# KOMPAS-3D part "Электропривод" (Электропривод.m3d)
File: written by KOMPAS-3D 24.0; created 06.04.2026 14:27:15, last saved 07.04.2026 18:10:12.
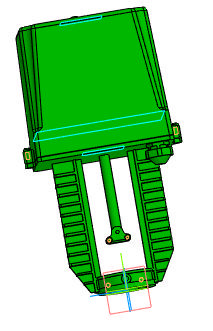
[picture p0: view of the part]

Document properties: Автор: R2D2; Полное имя файла: E:\Работа\Зайцев\Солянка\VSR1-13V-PED-F Клапан запорно-регулирующий DN.ru\DN80\исходные материалы\Электропривод.m3d

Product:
- Body: Тело 1  | qty 1
    Масса: 33.559685
- Body: Тело 2  | qty 1
    Масса: 33.559685
- Body: Тело 3  | qty 1
    Масса: 33.559685
- Component [standard]: Hexagon socket head cap screw ISO 4762 - М4 x 10  | qty 1  | Материал: Не определено (density 0 kg/m3); Масса: 0.0018; Рассекать на разрезах: no; source file: C:\Program Files\ASCON\KOMPAS-3D v24\Libs\PolynomLib\DATA\vault\Methods\Kompas\3D\PLib_Screw_DIN_7984_1500.m3d
- Component [standard]: Hexagon socket head cap screw ISO 4762 - М4 x 10  | qty 1  | Материал: Не определено (density 0 kg/m3); Масса: 0.0018; Рассекать на разрезах: no
- Component [standard]: Cheese head screw ISO 7048 - М5 x 10 - H  | qty 1  | Материал: Не определено (density 0 kg/m3); Масса: 0.00255; Рассекать на разрезах: no; source file: C:\Program Files\ASCON\KOMPAS-3D v24\Libs\PolynomLib\DATA\vault\Methods\Kompas\3D\PLib_Screw_ISO_7048_1500.m3d
- Component [standard]: Cheese head screw ISO 7048 - М5 x 10 - H  | qty 1  | Материал: Не определено (density 0 kg/m3); Масса: 0.00255; Рассекать на разрезах: no
- Component [standard]: (unnamed)  | qty 1  | Материал: Не определено (density 0 kg/m3); Масса: 0.00146; Рассекать на разрезах: no; additional columns: М6 x 10; Hexagon socket set screw; ISO 4026; source file: C:\Program Files\ASCON\KOMPAS-3D v24\Libs\PolynomLib\DATA\vault\Methods\Kompas\3D\PLib_Set_Screws_ISO_1100.m3d
- Component [standard]: (unnamed)  | qty 1  | Материал: Не определено (density 0 kg/m3); Масса: 0.00146; Рассекать на разрезах: no; additional columns: М6 x 10; Hexagon socket set screw; ISO 4026
- Component [detail]: Деталь  | qty 1  | Масса: 0.134709; Автор: R2D2; source file: ручка.m3d
- Component [detail]: Деталь  | qty 1  | Масса: 0.106559; Автор: R2D2; source file: кабельный зажим.m3d
- Part/product: Электропривод
    Масса: 0.101125

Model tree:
1. Низ
2. Элемент вращения:1
     Угол 1 = 360
3. Эскиз:4  (with: Ребро.Элемент вращения:1, Грань.Элемент вращения:1)
4. Элемент выдавливания:3
     Расстояние 1 = 35
5. Эскиз:9
6. Элемент выдавливания:6
     Расстояние 2 = 35
7. Эскиз:3  (with: Грань.Элемент вращения:1)
8. Элемент выдавливания:2
9. Эскиз:2  (with: Грань.Элемент вращения:1, Ребро.Элемент выдавливания:2)
10. Элемент выдавливания:1
11. Массив по концентрической сетке:1  (with: Элемент выдавливания:1, Эскиз:2, Грань.Элемент выдавливания:2)  (5 pattern instances)
     Шаг 2 = 360
12. Смещенная плоскость:1
     Расстояние = 327
13. Смещенная плоскость:2
     Расстояние = 169
14. крышка
15. Элемент выдавливания:4
     Расстояние 2 = 158
16. Уклон:1  (with: Грань.Элемент выдавливания:4)
     Угол уклона = 2
17. Эскиз:6  (with: Грань.Элемент выдавливания:4, Вершина.Элемент выдавливания:4)
18. Смещенная плоскость:3  (with: Грань.Элемент выдавливания:4)
     Расстояние = 128
19. Эскиз:7  (with: Ребро.Элемент выдавливания:4)
20. Элемент по сечениям:1
21. Скругление:26  (with: Ребро.Элемент выдавливания:4, Ребро.Элемент по сечениям:1, Грань.Элемент по сечениям:1)
     Радиус = 5
22. Массив по концентрической сетке:3  (with: Элемент по сечениям:1, Эскиз:6, Смещенная плоскость:3, Эскиз:7, Скругление:26)  (4 pattern instances)
     Шаг 2 = 360
23. Скругление:27  (with: Грань.Элемент выдавливания:4)
     Радиус = 5
24. уши  (with: Грань.Элемент выдавливания:4)
25. Элемент выдавливания:5
     Расстояние 2 = 15
26. Скругление:29  (with: Ребро.Элемент выдавливания:5)
     Радиус = 5
27. Эскиз:10  (with: Грань.Элемент выдавливания:4)
28. Элемент выдавливания:7
     Расстояние 1 = 0.5
29. Эскиз:11  (with: Грань.Элемент выдавливания:7, Ребро.Элемент выдавливания:4, Ребро.Скругление:26, Ребро.Элемент выдавливания:5, Ребро.Скругление:29)  (labels: Ребро.Скругление:26.Экземпляр ( 1, 4 ); Ребро.Скругление:26.Экземпляр ( 1, 3 ); Ребро.Скругление:26.Экземпляр ( 1, 2 ))
30. Элемент выдавливания:8
     Расстояние 1 = 5
31. РЕБРО  (with: Ребро.Элемент вращения:1, Ребро.Элемент выдавливания:8)
32. Элемент выдавливания:9
     Расстояние 1 = 4
33. Эскиз:13  (with: Ребро.Элемент выдавливания:9, Ребро.Элемент выдавливания:8, Грань.Элемент вращения:1, Вершина.Элемент вращения:1, Вершина.Элемент выдавливания:9, Ребро.Элемент вращения:1)
34. Элемент выдавливания:10
     Толщина стенки 2 = 3; Расстояние 1 = 20
35. Фаска:6  (with: Ребро.Элемент выдавливания:9)
     Угол = 60; Длина 1 = 20; Длина 2 = 34.641
36. Эскиз:14  (with: Вершина.Фаска:6, Ребро.Элемент выдавливания:10)
37. Элемент выдавливания:11
     Толщина стенки 1 = 3; Расстояние 1 = 20
38. Скругление:30  (with: Ребро.Элемент выдавливания:11)
     Радиус = 2
39. Массив по сетке:1  (with: Элемент выдавливания:11, Скругление:30, Ребро.Элемент выдавливания:9)  (10 pattern instances)
     Шаг 1 = 12; Угол раствора = 90
40. Эскиз:15  (with: Ребро.Элемент выдавливания:10, Ребро.Фаска:6, Ребро.Элемент выдавливания:11)
41. Элемент выдавливания:12
     Толщина стенки 2 = 2; Расстояние 1 = 20
42. Скругление:31  (with: Ребро.Элемент выдавливания:12)
     Радиус = 2
43. маятник  (with: Ребро.Элемент выдавливания:8)
44. Элемент вращения:2
     Угол 1 = 360
45. Эскиз:17  (with: Ребро.Элемент вращения:2)
46. Элемент выдавливания:13
     Расстояние 1 = 13
47. Скругление:32  (with: Ребро.Элемент выдавливания:13)
     Радиус = 4
48. Эскиз:18  (with: Ребро.Элемент выдавливания:13)
49. Элемент выдавливания:14
     Расстояние 1 = 24
50. Скругление:34  (with: Ребро.Элемент выдавливания:14)
     Радиус = 2
51. Скругление:35  (with: Ребро.Элемент выдавливания:13)
     Радиус = 2
52. Зеркальный массив:1
53. Экземпляр ( 1 )
54. Экземпляр ( 2 )  (with: Элемент выдавливания:9, Массив по сетке:1, Экземпляр ( 1 ), Элемент выдавливания:11, Скругление:30, Элемент выдавливания:12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)
55. Эскиз:19  (with: Грань.Элемент выдавливания:4, Ребро.Скругление:27)
56. Элемент выдавливания:16
     Расстояние 1 = 3
57. Скругление:36  (with: Ребро.Элемент выдавливания:16, Ребро.Скругление:27, Ребро.Скругление:26)  (labels: Ребро.Скругление:26.Экземпляр ( 1, 4 ); Ребро.Скругление:26.Экземпляр ( 1, 3 ); Ребро.Скругление:26.Экземпляр ( 1, 2 ))
     Радиус = 1.5
58. Эскиз:20  (with: Грань.Элемент выдавливания:4, Ребро.Скругление:27)
59. Элемент выдавливания:17
     Расстояние 2 = 10
60. Скругление:37  (with: Грань.Элемент выдавливания:17, Грань.Элемент выдавливания:13, Грань.Скругление:32, Грань.Элемент выдавливания:5, Грань.Скругление:29, Грань.Элемент выдавливания:6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)
     Радиус = 2; Расстояние = -4; Расстояние = -20; Расстояние = 20

Expressions: v238+0.5
Referenced files in C:\Program Files\ASCON\KOMPAS-3D v24\Libs\Pipeline\: StylesTemplate.a3d, TemplateHPH, InsulationStylesTemplate.a3d, Insulation
Referenced files in C:\Program Files\ASCON\KOMPAS-3D v24\Templates\: Констр. чертеж А3 гориз. перв. лист.cdt
Referenced files in E:\Работа\Зайцев\Солянка\VSR1-13V-PED-F Клапан запорно-регулирующий DN.ru\DN15\DN15 Kv0.16\исходные материалы\: 
Referenced files in C:\Program Files\ASCON\KOMPAS-3D v24\Libs\PolynomLib\DATA\vault\Methods\Kompas\3D\: PLib_Screw_DIN_7984_1500.m3d, PLib_Screw_ISO_7048_1500.m3d, PLib_Set_Screws_ISO_1100.m3d
Referenced files in E:\Работа\Зайцев\Солянка\VSR1-13V-PED-F Клапан запорно-регулирующий DN.ru\DN80\исходные материалы\: ручка.m3d, кабельный зажим.m3d
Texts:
  BOSimple***PART:60499af3-4b6a-c7f5-8cff-0a96383a042f***SHORTLOC:A259_235BDFABBEFC4171[0,7;10;4;-;Undefined]
  BOSimple***PART:5fbac98a-f0ab-87b8-89d4-94a9c7ed4dc2***SHORTLOC:B94B_D4FD7824BC314902[H;0,8;10;5;-;Undefined]
  BOSimple***PART:846f8b2b-3aaa-6f60-51af-14490994d85d***SHORTLOC:A259_4FF597E360DA469F[1;10;6;-;Undefined]
  Отводы ГОСТ 17375-2001
  Констр. чертеж А3 гориз. перв. лист.cdt
  Точка начала. Х
  Точка начала. Y
  Точка начала. Z
  Линейный размер с обрывом
  Hexagon socket head cap screw ISO 4762 - М4 x 10 (1)
  Hexagon socket head cap screw ISO 4762 - М4 x 10 (2)
  Cheese head screw ISO 7048 - М5 x 10 - H (1)
  Cheese head screw ISO 7048 - М5 x 10 - H (2)
  Деталь (1)
  Деталь (2)
  Плоскость XY.Начало координат
  Плоскость ZX.Начало координат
